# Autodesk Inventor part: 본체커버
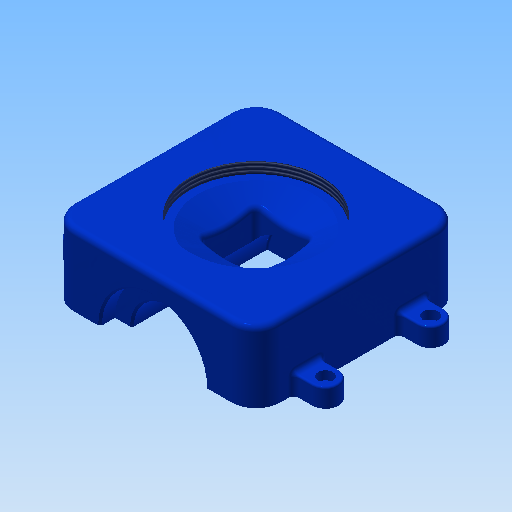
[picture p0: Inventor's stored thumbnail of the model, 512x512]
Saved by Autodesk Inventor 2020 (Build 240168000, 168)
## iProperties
Created: 2018-01
Part Number: 본체커버
Material: 알루미늄 6061
Document SubType Name: Modeling
Designer: mduedu
Density: 1 g/cm^3
Appearance: 선명 - 파란색
Author: mduedu
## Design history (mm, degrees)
sketch "스케치1"
  geometry: L1 (55, 55)-(-55, 55); L2 (-55, 55)-(-55, -55); L3 (-55, -55)-(55, -55); L4 (55, -55)-(55, 55); L5 (55, 55)-(-55, -55); L6 (-55, 55)-(55, -55); 1 further point
  constraints: 12 end point, 2 midpoint, 2 parallel, 1 horizontal, 1 perpendicular
  dimensions: "d0" = 110 distance of L3.end L2.end; "d1" = 110 distance of L2.end L1.end
extrude "돌출1" new body sketch "스케치1" distance "d2" = 38; taper "d3" = 0 deg
revolve "회전1" stored, may be unused: angle "d13" = 90 deg
fillet "모깎기1" dims "d14" = 1
fillet "모깎기2" dims "d15" = 13
fillet "모깎기3" dims "d16" = 3
sketch "스케치3"
  geometry: L1 (-15, -15)-(15, -15); L2 (15, -15)-(15, 15); L3 (15, 15)-(-15, 15); L4 (-15, 15)-(-15, -15); L5 (42, 55)-(-42, 55) reference; L6 (-15, -15)-(15, 15); L7 (15, -15)-(-15, 15); 2 further points
  constraints: 12 end point, 2 parallel, 1 horizontal, 1 midpoint, 1 perpendicular, 1 vertical alignment
  dimensions: "d19" = 30 distance of L3.end L1.start; "d20" = 30 distance between parallel lines of L2 L4; "d65" = 40 distance between parallel lines of L5 L3
extrude "돌출2" cut sketch "스케치3" extent not by distance; stored distance "d21" = 38; taper "d22" = 0 deg
fillet "모깎기4" dims "d23" = 3
sketch "스케치4"
  geometry: L1 (38, 35)-(32, 35); L2 (32, 35)-(32, 31); L3 (32, 31)-(25, 15); L4 (25, 15)-(25, 0); L5 (25, 0)-(38, 0); L6 (38, 0)-(38, 35); L7 (38, 42)-(38, -42) reference; 1 further point
  constraints: 12 end point, 2 parallel, 1 collinear, 1 horizontal, 1 horizontal alignment, 1 perpendicular
  dimensions: "d24" = 6 distance of L1.start L1.end; "d26" = 70 diameter of L1 L5; "d28" = 62 diameter of L2.end L5; "d29" = 30 diameter of L3.end L5; "d30" = 7 horizontal distance of L2.end L3.end
revolve "회전2" sketch "스케치4" stored, may be unused: angle "d31" = 90 deg
feature "스레드1" dims "d74" = 10, "d75" = 0
chamfer "모따기2" distance "d36" = 1; stored, may be unused: second distance "d37" = 2, angle "d38" = 45 deg
sketch "스케치5"
  geometry: L1 (-42, 55)-(-29, 55) reference; L2 (-55, -42)-(-55, 42) reference; L3 (42, -55)-(-42, -55) reference; L4 (55, 42)-(55, -42) reference; L5 (55, 35)-(65, 35); L6 (65, 21)-(55, 21); L7 (55, 21)-(55, 35); L8 (55, 42)-(55, -42) reference; L9 (28, 54)-(28, 47) reference; L10 (28, 47)-(20, 47) reference; L11 (19, 46)-(19, -24) reference; L12 (18, -25)-(7.5, -25) reference; L13 (7.5, -25)-(5.479, -28.5) reference; L14 (4.613, -29)-(-4.613, -29) reference; L15 (-5.479, -28.5)-(-7.5, -25) reference; L16 (-7.5, -25)-(-18, -25) reference; L17 (-19, -24)-(-19, 46) reference; L18 (-20, 47)-(-28, 47) reference; L19 (-28, 47)-(-28, 54) reference; L20 (19, 46)-(20, 47) reference; L21 (-20, 47)-(-19, 46) reference; L22 (-29, 55)-(-28, 54) reference; L23 (29, 55)-(42, 55) reference; L24 (28, 54)-(29, 55) reference; A1 r 13 centre (-42, 42) between (-42, 55) and (-55, 42) reference; A2 r 13 centre (-42, -42) between (-55, -42) and (-42, -55) reference; A3 r 13 centre (42, -42) between (42, -55) and (55, -42) reference; A4 r 13 centre (42, 42) between (55, 42) and (42, 55) reference; A5 r 7 centre (65, 28) between (65, 21) and (65, 35); A6 r 1 centre (18, -24) between (18, -25) and (19, -24) reference; A7 r 1 centre (4.613, -28) between (4.613, -29) and (5.479, -28.5) reference; A8 r 1 centre (-4.613, -28) between (-5.479, -28.5) and (-4.613, -29) reference; A9 r 1 centre (-18, -24) between (-19, -24) and (-18, -25) reference; 1 further point
  constraints: 6 end point, 2 point on circle, 2 tangent, 1 centre point, 1 collinear, 1 horizontal, 1 parallel, 1 point on line
  dimensions: "d39" = 14 distance between parallel lines of L6 L5; "d41" = 28 vertical distance of A5.centre point (0, 0); "d42" = 10 distance from line of A5.centre L4
extrude "돌출3" join sketch "스케치5" distance "d43" = 10; taper "d44" = 0 deg
fillet "모깎기6" dims "d45" = 1
fillet "모깎기7" dims "d46" = 3
sketch "스케치6"
  geometry: A1 r 7 centre (-65, 28) between (-65, 35) and (-65, 21) reference; A2 r 7 centre (-65, -28) between (-65, -21) and (-65, -35) reference; A3 r 7 centre (65, -28) between (65, -35) and (65, -21) reference; A4 r 7 centre (65, 28) between (65, 21) and (65, 35) reference; 5 further points
  constraints: 4 coincident
sketch "스케치7"
  geometry: 4 further points
  constraints: 4 other
hole "구멍1" sketch "스케치7" at (-65, 28), (65, 28), (-65, -28), (65, -28) diameter "d47" = 4.5; stored, may be unused: countersink angle "d51" = 90 deg, drill point angle "d53" = 0 deg; dims "d48" = 6, "d49" = 8, "d50" = 4.6, "d52" = 8
sketch "스케치9" dims "d66" = 46
  geometry: 3 further points
  constraints: 2 vertical alignment, 1 coincident, 2 other
hole "구멍2" sketch "스케치9" at (0, 23) diameter "d67" = 3.242; stored, may be unused: countersink angle "d71" = 90 deg, drill point angle "d73" = 118 deg; dims "d68" = 9, "d69" = 4, "d70" = 2, "d72" = 11
sketch "스케치8"
  geometry: L1 (-97, 35)-(-97, 0) reference; L2 (0, 38)-(-84, 38) reference; 2 further points
  constraints: 1 other
  dimensions: "d54" = 55 distance from line of point (-42, 23) L1; "d55" = 15 distance from line of point (-42, 23) L2
feature "엠보싱1" sketch "스케치8" dims "d0" = 110, "d1" = 110, "d56" = 0.5, "d57" = 0
node "솔리드1"
mirror "대칭1"
mirror "대칭2"
sketch "스케치2"
  geometry: L1 (-55, 55)-(55, 55) reference; L2 (-55, -55)-(-55, 55) reference; L3 (55, -55)-(-55, -55) reference; L4 (55, 55)-(55, -55) reference; L5 (0, 55)-(28, 55); L6 (19, 47)-(19, -25); L7 (19, -25)-(7.5, -25); L8 (0, -25.854)-(0, 55); L9 (7.5, -25)-(5.191, -29); L10 (5.191, -29)-(0, -29); L11 (0, -29)-(0, -25.854); L12 (19, 47)-(28, 47); L13 (28, 47)-(28, 55); 1 further point
  constraints: 18 end point, 2 horizontal, 2 perpendicular, 1 midpoint, 1 parallel, 1 point on line, 1 vertical
  dimensions: "d7" = 38 diameter of L6 L8; "d58" = 4 distance between parallel lines of L7 L10; "d59" = 30 deg angle of L8 L9; "d60" = 15 diameter of L7.end L8; "d61" = 56 diameter of L13 L8; "d62" = 8 distance of L12.end L5.end; "d63" = 84 distance between parallel lines of L10 L5
node "투영된 루프1"
node "투영된 루프2"
